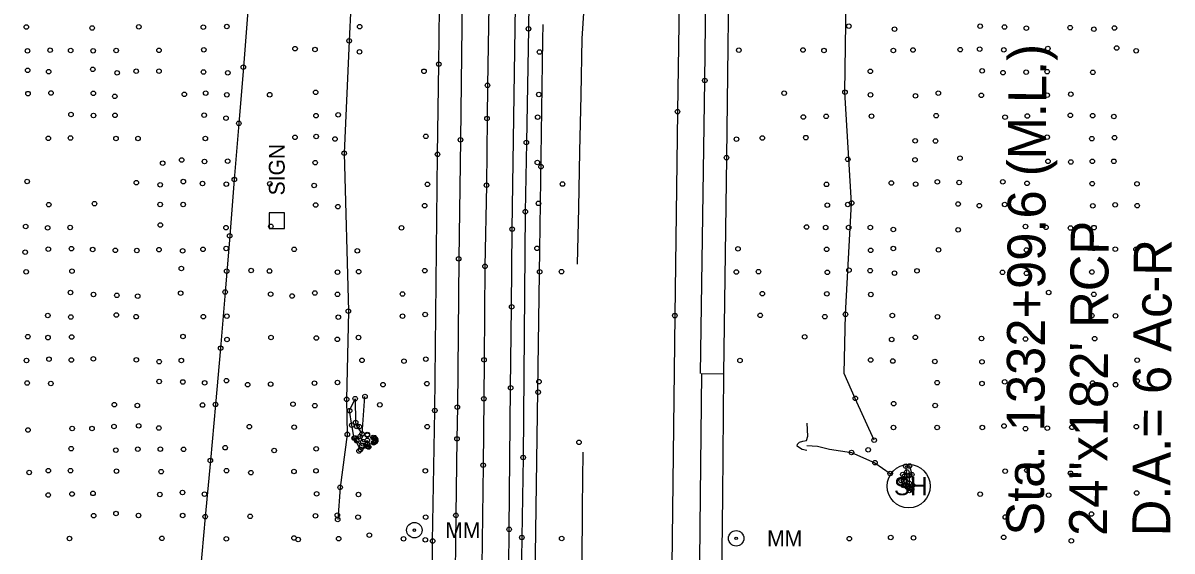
# Model space of a CAD drawing. Extents: x 20503438 to 20508873, y 7964251 to 7984667.
# Drawn here: x 20506371 to 20506880, y 7966053 to 7966287 of the extents above; entities that cross this region are included whole.
import ezdxf

# ---------------------------------------------------------------- set-up
doc = ezdxf.new("R2010")
doc.units = 0
for name, color, linetype in [('SurBreakLine', 7, 'Continuous'), ('SurConcreteSlab', 7, 'Continuous'), ('SurDrainageArrowDown', 7, 'Continuous'), ('SurDrainageArrowUp', 7, 'Continuous'), ('SurEdgeRoadPaved', 7, 'Continuous'), ('SurEdgeShoulderPaved', 7, 'Continuous'), ('SurGuardRailCable', 7, 'Continuous'), ('SurNaturalCells', 7, 'Continuous'), ('SurPointsNonDTM', 7, 'Continuous'), ('SurRoadPoints', 7, 'Continuous'), ('SurSurveyPoints', 7, 'Continuous'), ('SurTxtDrainage', 7, 'Continuous')]:
    doc.layers.add(name, color=color, linetype=linetype)

msp = doc.modelspace()

# ---------------------------------------------------------------- linework, layer by layer
at = {"layer": 'SurBreakLine'}
for points in [[(20506676.27, 7967436.58), (20506673.75, 7967260.63), (20506673.38, 7967229.74), (20506672.93, 7967188.92), (20506672.41, 7967153.72), (20506672.19, 7967124.04), (20506671.1, 7967048.34), (20506670.26, 7966945.33), (20506669.67, 7966906.46), (20506669.41, 7966871.04), (20506668.85, 7966836.8), (20506668.54, 7966801.73), (20506668.02, 7966767.22), (20506667.76, 7966729.81), (20506666.24, 7966623.69), (20506665.51, 7966587.93), (20506664.19, 7966486.04), (20506662.51, 7966335.32), (20506661.23, 7966248.03), (20506660.03, 7966157.63), (20506658.3, 7966009.76)], [(20506582.81, 7966724.92), (20506582.26, 7966677.31), (20506582.09, 7966663.27), (20506581.59, 7966615.11), (20506580.38, 7966502.13), (20506579.87, 7966469.3), (20506579.47, 7966429.21), (20506579.05, 7966404.24), (20506578.73, 7966381.34), (20506578.04, 7966321.61), (20506576.98, 7966259.67), (20506576.78, 7966244.96), (20506576.56, 7966215.41), (20506575.87, 7966179.43), (20506575.47, 7966138), (20506575.36, 7966120.77), (20506575.03, 7966091.32), (20506574.47, 7966046.48)], [(20506524.33, 7966099.4), (20506520.71, 7966098.29), (20506517.91, 7966103.33), (20506516.85, 7966109.08), (20506515.87, 7966115.5), (20506518.34, 7966120.79), (20506518.54, 7966110.27), (20506519.05, 7966108.49), (20506521.38, 7966105.16)], [(20506521.38, 7966105.16), (20506522.69, 7966121.79)], [(20506718.49, 7966097.81), (20506716.49, 7966098.25), (20506715.19, 7966099.04), (20506714.23, 7966099.69), (20506714.38, 7966100.67), (20506715.33, 7966101.57), (20506716.74, 7966102.04), (20506718.43, 7966102.3), (20506718.95, 7966104.15), (20506718.63, 7966109.88)]]:
    msp.add_lwpolyline(points, dxfattribs=at)
for points in [[(20506523.75, 7966102.32), (20506523.75, 7966099.6), (20506521.29, 7966099.88), (20506519.07, 7966102.09), (20506518.23, 7966103.41), (20506520.53, 7966104.04), (20506521.78, 7966101.72)], [(20506764.96, 7966080.6), (20506763.97, 7966080.14), (20506761.46, 7966082.36), (20506760.29, 7966084.46), (20506761.04, 7966087.19), (20506762.83, 7966088.28), (20506762.39, 7966090.86), (20506764.05, 7966090.99), (20506765.05, 7966087.15), (20506765.42, 7966082.37)], [(20506763.1, 7966081.62), (20506762.52, 7966082.44), (20506761.57, 7966084.28), (20506762.93, 7966086.64), (20506763.82, 7966086.68), (20506763.93, 7966083.3), (20506764.35, 7966081.47)]]:
    msp.add_lwpolyline(points, close=True, dxfattribs=at)
at = {"layer": 'SurConcreteSlab'}
msp.add_lwpolyline([(20506689.7, 7966746.61), (20506689.28, 7966704.08), (20506688.88, 7966672.82), (20506688.14, 7966636.15), (20506687.92, 7966599.43), (20506687.39, 7966571.12), (20506686.99, 7966548.42), (20506686.9, 7966542.73), (20506686.59, 7966522.86), (20506686.25, 7966494.65), (20506686.03, 7966477.61), (20506685.38, 7966428.04), (20506685.13, 7966404.1), (20506684.93, 7966380.11), (20506684.65, 7966363.47), (20506684.25, 7966338.35), (20506682.89, 7966227.64), (20506681.53, 7966131.86)], dxfattribs=at)
at = {"layer": 'SurDrainageArrowDown'}
for points in [[(20506616.88, 7966180.41), (20506617.4, 7966205.4), (20506617.92, 7966230.4), (20506618.45, 7966255.39), (20506618.97, 7966280.39), (20506620.54, 7966305.33), (20506622.35, 7966330.27), (20506622.07, 7966354.47), (20506621.79, 7966378.67), (20506621.52, 7966402.88), (20506621.24, 7966427.08), (20506620.96, 7966451.29), (20506620.68, 7966475.49), (20506621.28, 7966497.96), (20506622.23, 7966519.72), (20506623.18, 7966541.47), (20506623.65, 7966564.87), (20506623.65, 7966589.87), (20506623.79, 7966614.5), (20506624.24, 7966638.28), (20506624.7, 7966662.06), (20506625.16, 7966685.84), (20506625.61, 7966709.62), (20506625.94, 7966733.94)], [(20506523.75, 7966721.59), (20506524.08, 7966654.91), (20506523.46, 7966584.86), (20506526.32, 7966516.32), (20506520.79, 7966470.76), (20506521.88, 7966436.58), (20506518.64, 7966398.81), (20506514.26, 7966328.87), (20506517.2, 7966310.23), (20506515.68, 7966279.39), (20506513.5, 7966229.59), (20506515.33, 7966159.59), (20506514.55, 7966120.49), (20506514.84, 7966104.97), (20506511.67, 7966081.49), (20506510.59, 7966067.23)], [(20506470.8, 7966292.66), (20506468.79, 7966267.75), (20506466.78, 7966242.83), (20506464.76, 7966217.91), (20506462.75, 7966192.99), (20506460.74, 7966168.07), (20506458.72, 7966143.16), (20506456.48, 7966118.26), (20506454.18, 7966093.37), (20506451.89, 7966068.48), (20506449.59, 7966043.59)], [(20506619.2, 7966097.06), (20506618.97, 7966072.88), (20506618.74, 7966047.06), (20506618.49, 7966020.9), (20506618.27, 7965997.06), (20506618.04, 7965972.06), (20506617.81, 7965947.06), (20506617.58, 7965922.17), (20506617.16, 7965898.81), (20506616.37, 7965877.03), (20506615.69, 7965858.08), (20506614.95, 7965837.72), (20506614.27, 7965818.75), (20506613.48, 7965796.99), (20506612.75, 7965776.62), (20506612.14, 7965759.68)]]:
    msp.add_lwpolyline(points, dxfattribs=at)
at = {"layer": 'SurDrainageArrowUp'}
for points in [[(20506748.37, 7966102.43), (20506739.98, 7966120.94), (20506735.03, 7966132), (20506735.65, 7966158.21), (20506738.35, 7966207.5), (20506735.41, 7966256.62), (20506736, 7966297.52), (20506735.47, 7966344.97), (20506731.78, 7966371.15), (20506731.51, 7966393.42), (20506729.75, 7966442.32), (20506728.92, 7966490.67), (20506727.65, 7966541.52), (20506726.65, 7966586.02), (20506725.58, 7966633.07), (20506725.56, 7966682.41), (20506728.02, 7966733.71)], [(20506718.57, 7966099.98), (20506723.31, 7966099.83), (20506728.62, 7966098.37), (20506738.34, 7966096.95), (20506748.71, 7966092.43), (20506755.43, 7966087.63)]]:
    msp.add_lwpolyline(points, dxfattribs=at)
at = {"layer": 'SurEdgeRoadPaved'}
msp.add_line((20506671.99, 7966131.98), (20506681.61, 7966131.86), dxfattribs=at)
for points in [[(20506671.44, 7966131.99), (20506673.27, 7966261.84), (20506677.01, 7966570.96), (20506678.1, 7966642.03), (20506680.7, 7966833.13), (20506681.3, 7966886.9), (20506681.36, 7966892.52), (20506681.4, 7966895.33), (20506681.63, 7966918.21), (20506682.1, 7966969.83), (20506684.74, 7967192.21), (20506685.18, 7967235.97), (20506685.47, 7967264.79), (20506686.29, 7967317.73), (20506686.56, 7967334.59), (20506686.95, 7967373.78)], [(20506571.13, 7966726.82), (20506570.83, 7966695.86), (20506570.09, 7966639.42), (20506569.8, 7966614.3), (20506569.59, 7966591.6), (20506568.51, 7966495.95), (20506567.62, 7966430.5), (20506567.22, 7966396.52), (20506566.49, 7966355.87), (20506566.21, 7966336.33), (20506565, 7966235.53), (20506564.23, 7966182.81), (20506563.62, 7966117.05), (20506563.45, 7966102.98), (20506562.98, 7966069.12), (20506561.69, 7965956.65)], [(20506586.39, 7966046.04), (20506586.58, 7966062.88), (20506587.24, 7966125.61), (20506587.67, 7966161.5), (20506587.93, 7966195.96), (20506590.01, 7966334.68), (20506590.5, 7966371.48), (20506591.96, 7966478.18), (20506591.99, 7966480.99), (20506592.1, 7966489.42), (20506593.34, 7966593.17), (20506593.52, 7966612.66), (20506594.1, 7966668.59), (20506594.21, 7966677.21), (20506594.79, 7966724.61)], [(20506668.25, 7965801.58), (20506668.36, 7965811.28), (20506669.39, 7965901.02), (20506670.47, 7965991.32), (20506671.4, 7966077.96), (20506671.99, 7966131.98)], [(20506681.61, 7966131.86), (20506681.17, 7966077.72), (20506680.08, 7965991.13), (20506679.04, 7965894.12)]]:
    msp.add_lwpolyline(points, dxfattribs=at)
at = {"layer": 'SurEdgeShoulderPaved'}
for points in [[(20506552.57, 7966028.45), (20506552.68, 7966057.72), (20506553.65, 7966115.57), (20506554.86, 7966229.07), (20506555.39, 7966269.1), (20506555.74, 7966293.81), (20506557.36, 7966406.54), (20506557.74, 7966443.63), (20506558.13, 7966478.73), (20506558.55, 7966512.75), (20506558.65, 7966520.93), (20506559.14, 7966552.93), (20506559.31, 7966580.85), (20506559.62, 7966608.8), (20506561.22, 7966731.44)], [(20506600.27, 7966712.13), (20506599.16, 7966608.62), (20506599.01, 7966594.45), (20506598.05, 7966493.9), (20506597.53, 7966458.7), (20506596.92, 7966422.46), (20506595.16, 7966284.71), (20506594.2, 7966234.33), (20506593.75, 7966203.67), (20506592.8, 7966094.73), (20506592.19, 7966059.31), (20506591.79, 7966030.9)]]:
    msp.add_lwpolyline(points, dxfattribs=at)
at = {"layer": 'SurGuardRailCable'}
msp.add_lwpolyline([(20506613.34, 7964252.79), (20506601.5, 7964822.04), (20506598.64, 7964984.08), (20506597.55, 7965074.02), (20506596.61, 7965201.81), (20506594.34, 7965701.8), (20506594.71, 7965733.27), (20506595.45, 7965806.52), (20506596.03, 7965869.84), (20506597.23, 7965978.92), (20506600.18, 7966186.78), (20506601.51, 7966279.91), (20506601.63, 7966286.68)], dxfattribs=at)
at = {"layer": 'SurNaturalCells'}
msp.add_circle((20506763.65, 7966082.03), 9.59, dxfattribs=at)
at = {"layer": 'SurPointsNonDTM'}
for centre in [(20506600.69, 7966223.66), (20506599.46, 7966123.68), (20506617.55, 7966101.43)]:
    msp.add_circle(centre, 1, dxfattribs=at)
at = {"layer": 'SurRoadPoints'}
msp.add_lwpolyline([(20506487.04, 7966199.68), (20506487.04, 7966199.68), (20506487.04, 7966203.11), (20506480.18, 7966203.11), (20506480.18, 7966196.25), (20506487.04, 7966196.25), (20506487.04, 7966199.68)], dxfattribs=at)
for centre, radius in [((20506544.57, 7966062.54), 3.43), ((20506544.57, 7966062.54), 0.571), ((20506687.19, 7966058.91), 3.43), ((20506687.19, 7966058.91), 0.571)]:
    msp.add_circle(centre, radius, dxfattribs=at)
at = {"layer": 'SurSurveyPoints'}
for centre in [(20506372.58, 7966285.52), (20506401.8, 7966285.12), (20506422.43, 7966285.59), (20506451.02, 7966285.46), (20506461.43, 7966285.73), (20506520.33, 7966285.69), (20506595.16, 7966284.71), (20506737.14, 7966285.93), (20506757.4, 7966284.59), (20506795.33, 7966285.87), (20506806.12, 7966285.52), (20506815.81, 7966285.03), (20506835.2, 7966285.21), (20506845.74, 7966284.54), (20506854.84, 7966285.1), (20506515.68, 7966279.39), (20506373.11, 7966274.94), (20506383.13, 7966275.23), (20506392.28, 7966275.11), (20506402.23, 7966275.01), (20506412.44, 7966275.12), (20506431.42, 7966275.19), (20506451.25, 7966275.44), (20506491.71, 7966275.96), (20506500.53, 7966275.54), (20506520.28, 7966274.5), (20506600.03, 7966274.44), (20506688.38, 7966275.28), (20506716.83, 7966275.36), (20506726.1, 7966275.09), (20506756.87, 7966275.11), (20506765.57, 7966275.31), (20506786.5, 7966275.48), (20506795.11, 7966275.73), (20506805.79, 7966275.38), (20506825.35, 7966276.01), (20506855.8, 7966276.25), (20506864.46, 7966275), (20506373.19, 7966266.32), (20506402.05, 7966266.78), (20506468.79, 7966267.75), (20506555.39, 7966269.1), (20506382.49, 7966265.71), (20506412.84, 7966265.2), (20506421.31, 7966265.94), (20506431.4, 7966265.95), (20506451.12, 7966265.59), (20506461.87, 7966265.24), (20506548.86, 7966265.92), (20506673.27, 7966261.84), (20506746.68, 7966265.86), (20506796.2, 7966266.08), (20506805.44, 7966265.32), (20506815.71, 7966265.5), (20506825.02, 7966265.72), (20506845.25, 7966265.45), (20506383.52, 7966256.28), (20506402.3, 7966256.13), (20506452.11, 7966256.24), (20506500.83, 7966256.58), (20506576.98, 7966259.67), (20506708.48, 7966256.19), (20506735.41, 7966256.62), (20506776.79, 7966256.2), (20506373.33, 7966256.02), (20506411.8, 7966254.81), (20506442.6, 7966255.69), (20506461.48, 7966255.5), (20506480.48, 7966255.51), (20506599.75, 7966255.64), (20506746.73, 7966255.49), (20506766.65, 7966255), (20506795.86, 7966255.25), (20506825.02, 7966255.32), (20506835.49, 7966255.74), (20506392.4, 7966246.75), (20506402.36, 7966246.31), (20506411.93, 7966246.41), (20506451.41, 7966246.45), (20506500.97, 7966246.25), (20506510.84, 7966246.61), (20506661.23, 7966248.03), (20506727.08, 7966245.95), (20506747.2, 7966246.02), (20506775.83, 7966246.22), (20506816.2, 7966246.09), (20506835.32, 7966246.4), (20506845.19, 7966246.21), (20506461.07, 7966245.14), (20506466.78, 7966242.83), (20506576.78, 7966244.96), (20506599.2, 7966245.6), (20506716.95, 7966245.65), (20506806.37, 7966245.57), (20506854.6, 7966245.84), (20506382.38, 7966236.22), (20506392.19, 7966236.32), (20506412.34, 7966236.08), (20506422.08, 7966236.15), (20506451.94, 7966236.14), (20506491.68, 7966236.61), (20506501.09, 7966236.99), (20506509.38, 7966235.9), (20506549.67, 7966237.07), (20506687.31, 7966235.81), (20506698.81, 7966236.36), (20506718.05, 7966236.52), (20506825.03, 7966236.71), (20506844.8, 7966236.02), (20506854.89, 7966236.47), (20506565, 7966235.53), (20506594.2, 7966234.33), (20506766.56, 7966235.1), (20506775.53, 7966234.99), (20506441.44, 7966226.56), (20506451.58, 7966225.94), (20506461.84, 7966226.07), (20506513.5, 7966229.59), (20506554.86, 7966229.07), (20506682.89, 7966227.64), (20506736.68, 7966226.86), (20506766.43, 7966226.65), (20506786.37, 7966227.42), (20506825.4, 7966225.98), (20506835.52, 7966225.73), (20506845.04, 7966226.01), (20506854.55, 7966226.03), (20506433.05, 7966225.15), (20506500.64, 7966225.38), (20506599.1, 7966225.47), (20506372.94, 7966217.09), (20506421.35, 7966216.57), (20506431.94, 7966215.61), (20506442.16, 7966217.02), (20506450.7, 7966216.14), (20506461.22, 7966215.91), (20506464.76, 7966217.91), (20506480.52, 7966216.05), (20506550.36, 7966215.8), (20506576.56, 7966215.41), (20506610.24, 7966215.92), (20506727.24, 7966215.77), (20506755.97, 7966216.37), (20506766.73, 7966215.9), (20506776.35, 7966216.93), (20506786.01, 7966216.63), (20506805.35, 7966216.91), (20506816.12, 7966216.23), (20506845, 7966216.11), (20506864.86, 7966216.01), (20506500.14, 7966215.31), (20506382.55, 7966206.81), (20506402.81, 7966207.26), (20506431.93, 7966206.85), (20506442.13, 7966206.83), (20506500.84, 7966206.64), (20506510.69, 7966205.92), (20506549.12, 7966206.33), (20506599.56, 7966207.35), (20506727.59, 7966206.6), (20506736.65, 7966206.89), (20506738.35, 7966207.5), (20506785.55, 7966207.06), (20506794.93, 7966206.37), (20506806.2, 7966206.9), (20506845.23, 7966206.26), (20506855.15, 7966206.72), (20506864.93, 7966206.34), (20506593.75, 7966203.67), (20506372.33, 7966197.12), (20506382.04, 7966196.54), (20506392.02, 7966196.7), (20506431.97, 7966197.8), (20506461.1, 7966196.58), (20506480.99, 7966197.16), (20506538.88, 7966196.53), (20506587.93, 7966195.96), (20506718.4, 7966196.87), (20506726.87, 7966196.7), (20506737.02, 7966196.67), (20506746.66, 7966196.66), (20506756.83, 7966195.8), (20506785.58, 7966195.6), (20506815.4, 7966197.11), (20506824.52, 7966196.74), (20506835.36, 7966196.44), (20506845.8, 7966196.63), (20506462.75, 7966192.99), (20506372.12, 7966185.73), (20506382.34, 7966187.08), (20506392.59, 7966187.31), (20506402.02, 7966186.9), (20506412.05, 7966186.56), (20506421.56, 7966186.44), (20506431.43, 7966186.84), (20506441.88, 7966186.33), (20506450.89, 7966186.99), (20506461.16, 7966187.39), (20506491.31, 7966186.97), (20506519.3, 7966186.36), (20506598.95, 7966187.41), (20506688.03, 7966187.22), (20506727.31, 7966187.02), (20506746.8, 7966186.56), (20506756.83, 7966187.33), (20506776.86, 7966186.75), (20506815.83, 7966186.72), (20506845.66, 7966187.43), (20506855.2, 7966187.06), (20506864.4, 7966187), (20506564.23, 7966182.81), (20506372.53, 7966177.04), (20506392.85, 7966177.3), (20506441.31, 7966178.51), (20506461.39, 7966177.3), (20506472.22, 7966177.59), (20506480.39, 7966177.36), (20506510.51, 7966176.87), (20506519.87, 7966177.08), (20506549.18, 7966177.52), (20506575.87, 7966179.43), (20506600.09, 7966177.03), (20506609.77, 7966177.12), (20506687.26, 7966176.93), (20506697.09, 7966177.08), (20506727.61, 7966176.81), (20506737.21, 7966177.78), (20506746.57, 7966177.54), (20506757.38, 7966176.47), (20506767.35, 7966177.43), (20506805.24, 7966176.83), (20506815.84, 7966176.36), (20506844.85, 7966176.93), (20506392.16, 7966167.84), (20506402.39, 7966167), (20506412.7, 7966166.62), (20506421.98, 7966166.25), (20506440.98, 7966167.54), (20506460.74, 7966168.07), (20506480.88, 7966167.13), (20506490.39, 7966166.29), (20506500.45, 7966167.63), (20506510.53, 7966167.03), (20506539.31, 7966167.19), (20506698.81, 7966167.36), (20506727.41, 7966167.29), (20506746.87, 7966167), (20506825.7, 7966167.9), (20506845.7, 7966167.02), (20506515.33, 7966159.59), (20506587.67, 7966161.5), (20506382.1, 7966157.68), (20506392.31, 7966157), (20506412.52, 7966157.88), (20506421.26, 7966157.12), (20506451.03, 7966157.17), (20506461.45, 7966157.36), (20506510.87, 7966156.91), (20506539.35, 7966157.36), (20506549.33, 7966158.1), (20506660.03, 7966157.63), (20506697.85, 7966157.77), (20506726.48, 7966157.18), (20506735.65, 7966158.21), (20506756.43, 7966157.65), (20506776.44, 7966157.1), (20506844.8, 7966157.59), (20506855.31, 7966157.51), (20506373.29, 7966148.28), (20506382.22, 7966147.88), (20506392.68, 7966148.15), (20506442.03, 7966148.33), (20506461.51, 7966147.05), (20506481.05, 7966147.91), (20506501.16, 7966147.72), (20506510.47, 7966147.11), (20506519.81, 7966147.89), (20506717.58, 7966148.2), (20506756.11, 7966147.06), (20506766.61, 7966147.97), (20506795.91, 7966147.49), (20506815.41, 7966147.25), (20506846.05, 7966147.4), (20506458.72, 7966143.16), (20506372.68, 7966137.72), (20506382.63, 7966138.28), (20506392.55, 7966137.95), (20506402.33, 7966138.47), (20506421.37, 7966137.99), (20506431.48, 7966137.19), (20506441.31, 7966137.7), (20506521.39, 7966137.78), (20506539.99, 7966137.43), (20506549.62, 7966138.34), (20506575.47, 7966138), (20506688.87, 7966137.72), (20506746.8, 7966137.97), (20506756.6, 7966137.47), (20506775.26, 7966137.31), (20506796.16, 7966137.12), (20506864.9, 7966137.89), (20506461.29, 7966128.78), (20506372.99, 7966127.74), (20506383.46, 7966127.52), (20506431.49, 7966128.41), (20506441.98, 7966128.23), (20506451.62, 7966127.79), (20506470.67, 7966127.02), (20506480.87, 7966127.27), (20506500.29, 7966127.66), (20506510.48, 7966128), (20506530.65, 7966127.02), (20506550.14, 7966127.45), (20506587.24, 7966125.61), (20506599.79, 7966128.33), (20506776.28, 7966127.91), (20506796.12, 7966127.5), (20506806.21, 7966128.26), (20506845.19, 7966127.73), (20506855.33, 7966126.98), (20506864.94, 7966128.64), (20506514.55, 7966120.49), (20506518.34, 7966120.79), (20506522.69, 7966121.79), (20506575.36, 7966120.77), (20506739.98, 7966120.94), (20506756.99, 7966118.58), (20506411.59, 7966118.14), (20506421.83, 7966117.81), (20506450.71, 7966117.97), (20506456.48, 7966118.26), (20506490.77, 7966118.39), (20506500.46, 7966117.7), (20506515.87, 7966115.5), (20506529.27, 7966118.07), (20506553.65, 7966115.57), (20506563.62, 7966117.05), (20506775.35, 7966117.79), (20506411.44, 7966108.48), (20506422.41, 7966108.8), (20506471.41, 7966108.38), (20506516.85, 7966109.08), (20506518.54, 7966110.27), (20506519.05, 7966108.49), (20506520.16, 7966108.4), (20506550.27, 7966108.42), (20506805.89, 7966108.71), (20506864.57, 7966108.39), (20506373.32, 7966106.92), (20506392.92, 7966107.59), (20506401.69, 7966107.55), (20506431.31, 7966107.8), (20506491.33, 7966108.19), (20506514.84, 7966104.97), (20506517.91, 7966103.33), (20506518.23, 7966103.41), (20506520.53, 7966104.04), (20506521.38, 7966105.16), (20506523.73, 7966104.9), (20506523.76, 7966104.63), (20506526.28, 7966103.6), (20506526.94, 7966103.51), (20506756.9, 7966108.03), (20506776.24, 7966108.04), (20506796.26, 7966108.01), (20506815.41, 7966107.51), (20506825.09, 7966107.72), (20506835.99, 7966108.12), (20506392.47, 7966098.63), (20506421.99, 7966098.43), (20506432.01, 7966098.45), (20506442.28, 7966098.36), (20506460.75, 7966099.06), (20506501.09, 7966098.56), (20506519.07, 7966102.09), (20506520.71, 7966098.29), (20506521.29, 7966099.88), (20506521.78, 7966101.72), (20506523.75, 7966102.32), (20506523.75, 7966099.6), (20506523.78, 7966100.74), (20506523.79, 7966100.42), (20506524.33, 7966099.4), (20506526.53, 7966101.21), (20506526.82, 7966101.53), (20506527.18, 7966102.93), (20506527.19, 7966101.64), (20506527.31, 7966102.2), (20506527.37, 7966102.91), (20506527.41, 7966102.09), (20506563.45, 7966102.98), (20506748.37, 7966102.43), (20506412.29, 7966098.01), (20506454.18, 7966093.37), (20506482.48, 7966097.82), (20506520.01, 7966097.63), (20506592.8, 7966094.73), (20506738.34, 7966096.95), (20506745.73, 7966098.13), (20506373.89, 7966088.11), (20506382.36, 7966088.91), (20506392.19, 7966088.93), (20506412.53, 7966088.71), (20506432.35, 7966088.48), (20506461.31, 7966088.89), (20506491.23, 7966088.55), (20506500.96, 7966088.85), (20506549.45, 7966088.79), (20506575.03, 7966091.32), (20506748.71, 7966092.43), (20506762.39, 7966090.86), (20506762.83, 7966088.28), (20506764.05, 7966090.99), (20506806.39, 7966088.68), (20506816.04, 7966089.02), (20506472.13, 7966087.99), (20506755.43, 7966087.63), (20506760.29, 7966084.46), (20506761.04, 7966087.19), (20506761.57, 7966084.28), (20506762.93, 7966086.64), (20506763.82, 7966086.68), (20506763.93, 7966083.3), (20506765.05, 7966087.15), (20506835.39, 7966087.75), (20506382.32, 7966078.1), (20506392.88, 7966078.56), (20506402.14, 7966078.82), (20506431.77, 7966078.36), (20506441.81, 7966079.23), (20506451.55, 7966078.51), (20506501.27, 7966078.64), (20506511.67, 7966081.49), (20506519.78, 7966078.3), (20506761.46, 7966082.36), (20506762.52, 7966082.44), (20506763.1, 7966081.62), (20506763.97, 7966080.14), (20506764.35, 7966081.47), (20506764.96, 7966080.6), (20506765.42, 7966082.37), (20506795.34, 7966078.48), (20506825.69, 7966078.04), (20506864.7, 7966079.01), (20506402.44, 7966068.96), (20506412.36, 7966069.89), (20506422.32, 7966069.06), (20506441.91, 7966068.99), (20506451.89, 7966068.48), (20506471.8, 7966068.69), (20506500.73, 7966068.87), (20506510.46, 7966069.16), (20506519.63, 7966068.3), (20506549.61, 7966068.3), (20506562.98, 7966069.12), (20506806.51, 7966068.33), (20506844.64, 7966069.69), (20506510.59, 7966067.23), (20506586.58, 7966062.88), (20506391.7, 7966058.81), (20506432.68, 7966058.92), (20506461.24, 7966058.7), (20506491.22, 7966059.07), (20506493.06, 7966058.37), (20506511.01, 7966058.73), (20506524.63, 7966060.31), (20506539.79, 7966058.7), (20506549.42, 7966058.28), (20506552.68, 7966057.72), (20506592.19, 7966059.31), (20506609.87, 7966058.83), (20506737.37, 7966058.75), (20506755.7, 7966059.3), (20506765.77, 7966059.1), (20506805.73, 7966059.33), (20506835.71, 7966057.82)]:
    msp.add_circle(centre, 1, dxfattribs=at)

# ---------------------------------------------------------------- texts
at = {"layer": 'SurNaturalCells'}
msp.add_text('SH', height=7.995, rotation=360, dxfattribs=at).set_placement((20506757.13, 7966078.03))
at = {"layer": 'SurRoadPoints'}
for s, rotation, p in [('SIGN', 89.9987, (20506487.11, 7966210.89)), ('MM', 360, (20506558.28, 7966059.04)), ('MM', 360, (20506700.9, 7966055.42))]:
    msp.add_text(s, height=6.995, rotation=rotation, dxfattribs=at).set_placement(p)
at = {"layer": 'SurTxtDrainage'}
for s, p in [('Sta. 1332+99.6 (M.L.)', (20506823.55, 7966060.08)), ('24"x182\' RCP', (20506851.55, 7966059.93)), ('D.A.= 6 Ac-R', (20506879.55, 7966059.78))]:
    msp.add_text(s, height=16.8, rotation=89.6917, dxfattribs=at).set_placement(p)

doc.saveas('drawing.dxf')
